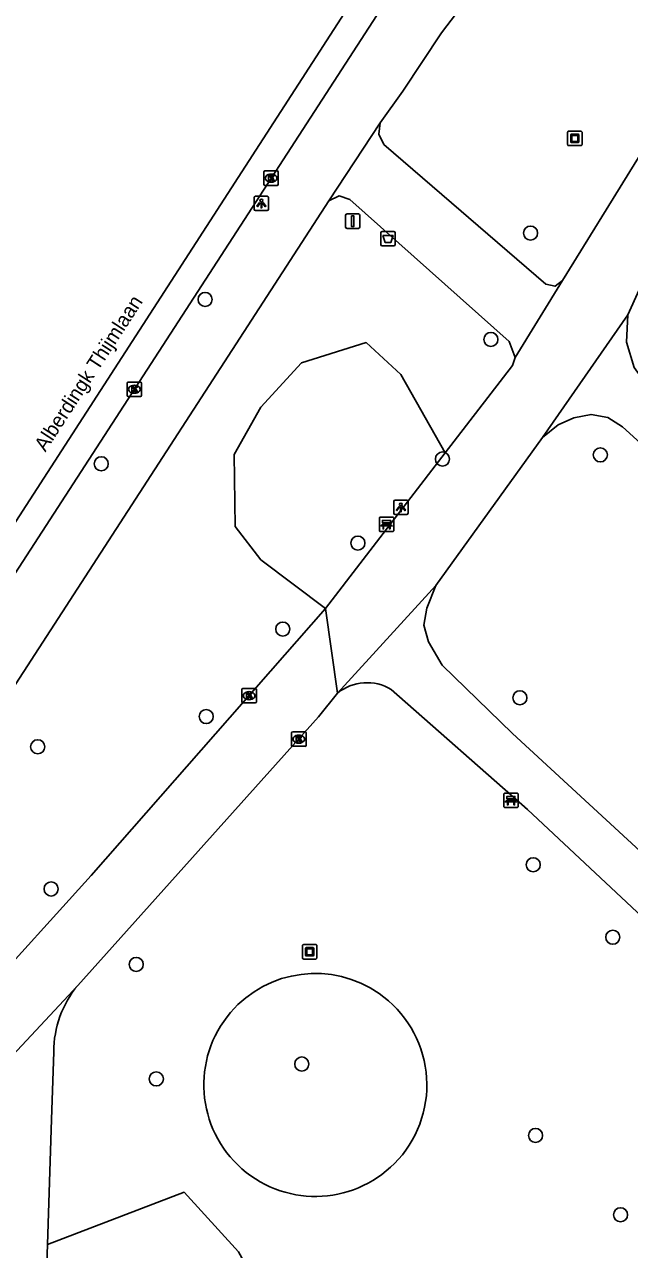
# Model space of a CAD drawing. Extents: x 161402 to 161933, y 381650 to 382313.
# Drawn here: x 161545.5 to 161587.5, y 381991 to 382075.9 of the extents above; entities that cross this region are included whole.
import ezdxf

# ---------------------------------------------------------------- set-up
doc = ezdxf.new("R2010")
doc.units = 0
for name, color, linetype in [('IMGEO_Afvalbak', 7, 'Continuous'), ('IMGEO_Bank', 7, 'Continuous'), ('IMGEO_Boom', 7, 'Continuous'), ('IMGEO_Groenvoorziening', 7, 'Continuous'), ('IMGEO_Kolk', 7, 'Continuous'), ('IMGEO_Kunstobject', 7, 'Continuous'), ('IMGEO_Lichtpunt', 7, 'Continuous'), ('IMGEO_Openbare_ruimte_label', 7, 'Continuous'), ('IMGEO_Rijbaan_lokaal_gesloten', 7, 'Continuous'), ('IMGEO_Verkeersbordpaal', 7, 'Continuous'), ('IMGEO_Voetpad_gesloten', 7, 'Continuous'), ('IMGEO_Voetpad_open', 7, 'Continuous')]:
    doc.layers.add(name, color=color, linetype=linetype)

msp = doc.modelspace()

# ---------------------------------------------------------------- linework, layer by layer
at = {"layer": 'IMGEO_Afvalbak'}
for p, q in [((161570.326, 382061.557), (161571.116, 382061.557)), ((161571.116, 382061.557), (161570.326, 382061.557)), ((161570.226, 382060.657), (161570.226, 382061.457)), ((161570.226, 382061.457), (161570.226, 382060.657)), ((161571.216, 382061.457), (161571.216, 382060.657)), ((161571.216, 382060.657), (161571.216, 382061.457)), ((161571.116, 382060.557), (161570.326, 382060.557)), ((161570.326, 382060.557), (161571.116, 382060.557))]:
    msp.add_line(p, q, dxfattribs=at)
msp.add_lwpolyline([(161570.369, 382061.271), (161571.073, 382061.271), (161570.924, 382060.801), (161570.518, 382060.801), (161570.369, 382061.271)], dxfattribs=at)
for centre, start, end in [((161570.326, 382061.457), 90, 180), ((161570.326, 382061.457), 90, 180), ((161571.116, 382061.457), 0, 90), ((161571.116, 382061.457), 360, 90), ((161570.326, 382060.657), 180, 270), ((161570.326, 382060.657), 180, 270), ((161571.116, 382060.657), 270, 0), ((161571.116, 382060.657), 270, 0)]:
    msp.add_arc(centre, 0.1, start, end, dxfattribs=at)
at = {"layer": 'IMGEO_Bank'}
for p, q in [((161570.122, 382040.825), (161570.122, 382041.666)), ((161570.122, 382041.666), (161570.122, 382040.825)), ((161570.197, 382041.75), (161571.038, 382041.75)), ((161571.038, 382041.75), (161570.197, 382041.75)), ((161570.431, 382041.256), (161570.431, 382041.362)), ((161570.475, 382041.362), (161570.475, 382041.256)), ((161570.763, 382041.368), (161570.481, 382041.368)), ((161570.481, 382041.25), (161570.763, 382041.25)), ((161570.769, 382041.256), (161570.769, 382041.362)), ((161570.813, 382041.362), (161570.813, 382041.256)), ((161571.122, 382041.675), (161571.122, 382040.834)), ((161571.122, 382040.834), (161571.122, 382041.675)), ((161571.047, 382040.75), (161570.206, 382040.75)), ((161570.206, 382040.75), (161571.047, 382040.75)), ((161570.819, 382041.148), (161570.426, 382041.148)), ((161578.746, 382021.695), (161578.746, 382022.536)), ((161578.746, 382022.536), (161578.746, 382021.695)), ((161578.821, 382022.62), (161579.662, 382022.62)), ((161579.662, 382022.62), (161578.821, 382022.62)), ((161579.746, 382022.545), (161579.746, 382021.704)), ((161579.746, 382021.704), (161579.746, 382022.545)), ((161579.443, 382022.018), (161579.05, 382022.018)), ((161579.055, 382022.126), (161579.055, 382022.232)), ((161579.099, 382022.232), (161579.099, 382022.126)), ((161579.387, 382022.238), (161579.105, 382022.238)), ((161579.105, 382022.12), (161579.387, 382022.12)), ((161579.393, 382022.126), (161579.393, 382022.232)), ((161579.437, 382022.232), (161579.437, 382022.126)), ((161579.671, 382021.62), (161578.83, 382021.62)), ((161578.83, 382021.62), (161579.671, 382021.62))]:
    msp.add_line(p, q, dxfattribs=at)
for points in [[(161570.369, 382041.148), (161570.227, 382041.148), (161570.339, 382041.25), (161570.425, 382041.25)], [(161570.425, 382041.368), (161570.339, 382041.368), (161570.339, 382041.529), (161570.902, 382041.529), (161570.902, 382041.368), (161570.819, 382041.368)], [(161570.819, 382041.25), (161570.902, 382041.25), (161571.014, 382041.148), (161570.875, 382041.148)], [(161570.419, 382041.141), (161570.419, 382040.934), (161570.376, 382040.934), (161570.376, 382041.141)], [(161570.869, 382041.141), (161570.869, 382040.934), (161570.825, 382040.934), (161570.825, 382041.141)], [(161578.993, 382022.018), (161578.851, 382022.018), (161578.963, 382022.12), (161579.049, 382022.12)], [(161579.049, 382022.238), (161578.963, 382022.238), (161578.963, 382022.399), (161579.526, 382022.399), (161579.526, 382022.238), (161579.443, 382022.238)], [(161579.043, 382022.011), (161579.043, 382021.804), (161579, 382021.804), (161579, 382022.011)], [(161579.443, 382022.12), (161579.526, 382022.12), (161579.638, 382022.018), (161579.499, 382022.018)], [(161579.493, 382022.011), (161579.493, 382021.804), (161579.449, 382021.804), (161579.449, 382022.011)]]:
    msp.add_lwpolyline(points, dxfattribs=at)
for centre, radius, start, end in [((161570.2, 382041.672), 0.0779, 92.4484, 184.28452), ((161570.2, 382041.672), 0.0779, 92.4484, 184.28452), ((161570.424, 382041.361), 0.00671, 2.89567, 87.10433), ((161570.424, 382041.257), 0.00671, 272.89567, 357.10433), ((161570.481, 382041.361), 0.00671, 92.89567, 177.10433), ((161570.481, 382041.257), 0.00671, 182.89567, 267.10433), ((161570.763, 382041.361), 0.00671, 2.89567, 87.10433), ((161570.763, 382041.257), 0.00671, 272.89567, 357.10433), ((161570.82, 382041.361), 0.00671, 92.89567, 177.10433), ((161570.82, 382041.257), 0.00671, 182.89567, 267.10433), ((161571.044, 382041.672), 0.0779, 2.4484, 94.28452), ((161571.044, 382041.672), 0.0779, 2.4484, 94.28452), ((161570.2, 382040.828), 0.0779, 182.4484, 274.28452), ((161570.2, 382040.828), 0.0779, 182.4484, 274.28452), ((161570.369, 382041.141), 0.00671, 2.89567, 87.10433), ((161570.426, 382041.141), 0.00671, 92.89567, 177.10433), ((161570.818, 382041.141), 0.00671, 2.89567, 87.10433), ((161570.875, 382041.141), 0.00671, 92.89567, 177.10433), ((161571.044, 382040.828), 0.0779, 272.4484, 4.28452), ((161571.044, 382040.828), 0.0779, 272.4484, 4.28452), ((161578.824, 382022.542), 0.0779, 92.4484, 184.28452), ((161578.824, 382022.542), 0.0779, 92.4484, 184.28452), ((161579.668, 382022.542), 0.0779, 2.4484, 94.28452), ((161579.668, 382022.542), 0.0779, 2.4484, 94.28452), ((161578.824, 382021.698), 0.0779, 182.4484, 274.28452), ((161578.824, 382021.698), 0.0779, 182.4484, 274.28452), ((161578.993, 382022.011), 0.00671, 2.89567, 87.10433), ((161579.05, 382022.011), 0.00671, 92.89567, 177.10433), ((161579.048, 382022.231), 0.00671, 2.89567, 87.10433), ((161579.048, 382022.127), 0.00671, 272.89567, 357.10433), ((161579.105, 382022.231), 0.00671, 92.89567, 177.10433), ((161579.105, 382022.127), 0.00671, 182.89567, 267.10433), ((161579.387, 382022.231), 0.00671, 2.89567, 87.10433), ((161579.387, 382022.127), 0.00671, 272.89567, 357.10433), ((161579.444, 382022.231), 0.00671, 92.89567, 177.10433), ((161579.444, 382022.127), 0.00671, 182.89567, 267.10433), ((161579.442, 382022.011), 0.00671, 2.89567, 87.10433), ((161579.499, 382022.011), 0.00671, 92.89567, 177.10433), ((161579.668, 382021.698), 0.0779, 272.4484, 4.28452), ((161579.668, 382021.698), 0.0779, 272.4484, 4.28452)]:
    msp.add_arc(centre, radius, start, end, dxfattribs=at)
at = {"layer": 'IMGEO_Boom'}
for centre in [(161580.604, 382061.45), (161558.047, 382056.845), (161577.855, 382054.076), (161574.5, 382045.785), (161585.441, 382046.074), (161550.846, 382045.454), (161568.634, 382039.959), (161563.429, 382033.996), (161579.862, 382029.231), (161558.123, 382027.931), (161546.441, 382025.837), (161580.786, 382017.659), (161547.37, 382015.978), (161586.303, 382012.631), (161553.269, 382010.749), (161564.748, 382003.843), (161554.661, 382002.809), (161580.95, 381998.893), (161586.845, 381993.392)]:
    msp.add_circle(centre, 0.489, dxfattribs=at)
at = {"layer": 'IMGEO_Groenvoorziening'}
for points in [[(161566.397, 382035.429), (161561.912, 382038.8), (161560.125, 382041.115), (161560.053, 382046.091), (161561.918, 382049.386), (161564.736, 382052.445), (161569.199, 382053.861), (161571.62, 382051.637), (161574.693, 382046.208)], [(161547.11, 381991.32), (161556.598, 381994.953), (161560.35, 381990.824), (161562.832, 381986.367), (161564.352, 381977.941)]]:
    msp.add_lwpolyline(points, dxfattribs=at)
for centre, radius, start, end in [((161565.687, 382002.391), 7.731, 55.08218, 139.41843), ((161565.685, 382002.391), 7.732, 318.21125, 55.07186), ((161565.689, 382002.394), 7.731, 139.44695, 318.1791)]:
    msp.add_arc(centre, radius, start, end, dxfattribs=at)
at = {"layer": 'IMGEO_Kolk'}
for p, q in [((161562.118, 382064.83), (161562.118, 382065.682)), ((161562.193, 382065.756), (161563.045, 382065.756)), ((161562.629, 382064.976), (161562.604, 382064.976)), ((161562.606, 382065.536), (161562.631, 382065.536)), ((161563.119, 382065.682), (161563.119, 382064.83)), ((161563.045, 382064.756), (161562.193, 382064.756)), ((161552.636, 382050.194), (161552.636, 382051.046)), ((161552.711, 382051.12), (161553.563, 382051.12)), ((161553.124, 382050.9), (161553.149, 382050.9)), ((161553.637, 382051.046), (161553.637, 382050.194)), ((161553.563, 382050.12), (161552.711, 382050.12)), ((161553.147, 382050.34), (161553.122, 382050.34)), ((161560.595, 382028.951), (161560.595, 382029.803)), ((161560.67, 382029.877), (161561.522, 382029.877)), ((161561.083, 382029.657), (161561.108, 382029.657)), ((161561.596, 382029.803), (161561.596, 382028.951)), ((161561.522, 382028.877), (161560.67, 382028.877)), ((161561.106, 382029.097), (161561.081, 382029.097)), ((161564.039, 382025.941), (161564.039, 382026.793)), ((161564.114, 382026.867), (161564.966, 382026.867)), ((161565.04, 382026.793), (161565.04, 382025.941)), ((161564.55, 382026.087), (161564.525, 382026.087)), ((161564.527, 382026.647), (161564.552, 382026.647)), ((161564.966, 382025.867), (161564.114, 382025.867))]:
    msp.add_line(p, q, dxfattribs=at)
for points in [[(161562.118, 382064.83), (161562.118, 382065.682)], [(161562.193, 382065.756), (161563.045, 382065.756)], [(161562.439, 382065.456), (161562.562, 382065.456), (161562.562, 382065.305), (161562.692, 382065.456), (161562.856, 382065.456), (161562.71, 382065.305), (161562.863, 382065.056), (161562.711, 382065.056), (161562.626, 382065.22), (161562.562, 382065.153), (161562.562, 382065.056), (161562.439, 382065.056), (161562.439, 382065.456)], [(161563.119, 382065.682), (161563.119, 382064.83)], [(161563.045, 382064.756), (161562.193, 382064.756)], [(161552.636, 382050.194), (161552.636, 382051.046)], [(161552.711, 382051.12), (161553.563, 382051.12)], [(161552.957, 382050.82), (161553.08, 382050.82), (161553.08, 382050.669), (161553.21, 382050.82), (161553.374, 382050.82), (161553.228, 382050.669), (161553.381, 382050.42), (161553.229, 382050.42), (161553.144, 382050.584), (161553.08, 382050.517), (161553.08, 382050.42), (161552.957, 382050.42), (161552.957, 382050.82)], [(161553.637, 382051.046), (161553.637, 382050.194)], [(161553.563, 382050.12), (161552.711, 382050.12)], [(161560.595, 382028.951), (161560.595, 382029.803)], [(161560.67, 382029.877), (161561.522, 382029.877)], [(161560.916, 382029.577), (161561.039, 382029.577), (161561.039, 382029.426), (161561.169, 382029.577), (161561.333, 382029.577), (161561.187, 382029.426), (161561.34, 382029.177), (161561.188, 382029.177), (161561.103, 382029.341), (161561.039, 382029.274), (161561.039, 382029.177), (161560.916, 382029.177), (161560.916, 382029.577)], [(161561.596, 382029.803), (161561.596, 382028.951)], [(161561.522, 382028.877), (161560.67, 382028.877)], [(161564.039, 382025.941), (161564.039, 382026.793)], [(161564.114, 382026.867), (161564.966, 382026.867)], [(161565.04, 382026.793), (161565.04, 382025.941)], [(161564.36, 382026.567), (161564.483, 382026.567), (161564.483, 382026.416), (161564.613, 382026.567), (161564.777, 382026.567), (161564.631, 382026.416), (161564.784, 382026.167), (161564.632, 382026.167), (161564.547, 382026.331), (161564.483, 382026.264), (161564.483, 382026.167), (161564.36, 382026.167), (161564.36, 382026.567)], [(161564.966, 382025.867), (161564.114, 382025.867)]]:
    msp.add_lwpolyline(points, dxfattribs=at)
for centre, start, end in [((161562.195, 382065.68), 91.55205, 178.44795), ((161562.195, 382065.68), 91.55205, 178.44795), ((161563.043, 382065.68), 1.55205, 88.44795), ((161563.043, 382065.68), 1.55205, 88.44795), ((161562.195, 382064.832), 181.55205, 268.44795), ((161562.195, 382064.832), 181.55205, 268.44795), ((161563.043, 382064.832), 271.55205, 358.44795), ((161563.043, 382064.832), 271.55205, 358.44795), ((161552.713, 382051.044), 91.55205, 178.44795), ((161552.713, 382051.044), 91.55205, 178.44795), ((161553.561, 382051.044), 1.55205, 88.44795), ((161553.561, 382051.044), 1.55205, 88.44795), ((161552.713, 382050.196), 181.55205, 268.44795), ((161552.713, 382050.196), 181.55205, 268.44795), ((161553.561, 382050.196), 271.55205, 358.44795), ((161553.561, 382050.196), 271.55205, 358.44795), ((161560.672, 382029.801), 91.55205, 178.44795), ((161560.672, 382029.801), 91.55205, 178.44795), ((161561.52, 382029.801), 1.55205, 88.44795), ((161561.52, 382029.801), 1.55205, 88.44795), ((161560.672, 382028.953), 181.55205, 268.44795), ((161560.672, 382028.953), 181.55205, 268.44795), ((161561.52, 382028.953), 271.55205, 358.44795), ((161561.52, 382028.953), 271.55205, 358.44795), ((161564.116, 382026.791), 91.55205, 178.44795), ((161564.116, 382026.791), 91.55205, 178.44795), ((161564.964, 382026.791), 1.55205, 88.44795), ((161564.964, 382026.791), 1.55205, 88.44795), ((161564.116, 382025.943), 181.55205, 268.44795), ((161564.116, 382025.943), 181.55205, 268.44795), ((161564.964, 382025.943), 271.55205, 358.44795), ((161564.964, 382025.943), 271.55205, 358.44795)]:
    msp.add_arc(centre, 0.0765, start, end, dxfattribs=at)
for centre, major_axis, ratio, start_param, end_param in [((161562.605, 382065.256), (-0.387, 0.002), 0.722429, 4.712389, 7.853982), ((161562.63, 382065.256), (-0.39, 0.002), 0.717154, 1.570796, 4.712389), ((161553.123, 382050.62), (-0.387, 0.002), 0.722429, 4.712389, 7.853982), ((161553.148, 382050.62), (-0.39, 0.002), 0.717154, 1.570796, 4.712389), ((161561.082, 382029.377), (-0.387, 0.002), 0.722429, 4.712389, 7.853982), ((161561.107, 382029.377), (-0.39, 0.002), 0.717154, 1.570796, 4.712389), ((161564.526, 382026.367), (-0.387, 0.002), 0.722429, 4.712389, 7.853982), ((161564.551, 382026.367), (-0.39, 0.002), 0.717154, 1.570796, 4.712389)]:
    msp.add_ellipse(centre, major_axis=major_axis, ratio=ratio, start_param=start_param, end_param=end_param, dxfattribs=at)
at = {"layer": 'IMGEO_Kunstobject'}
for p, q in [((161583.173, 382068.427), (161583.173, 382067.586)), ((161583.173, 382068.427), (161583.173, 382067.586)), ((161584.089, 382068.511), (161583.248, 382068.511)), ((161584.089, 382068.511), (161583.248, 382068.511)), ((161584.173, 382067.595), (161584.173, 382068.436)), ((161584.173, 382067.595), (161584.173, 382068.436)), ((161583.257, 382067.511), (161584.098, 382067.511)), ((161583.257, 382067.511), (161584.098, 382067.511)), ((161583.387, 382067.775), (161583.387, 382068.249)), ((161583.437, 382068.299), (161583.911, 382068.299)), ((161583.911, 382067.725), (161583.437, 382067.725)), ((161583.467, 382068.199), (161583.467, 382067.825)), ((161583.861, 382068.219), (161583.487, 382068.219)), ((161583.487, 382067.805), (161583.861, 382067.805)), ((161583.881, 382067.825), (161583.881, 382068.199)), ((161583.961, 382068.249), (161583.961, 382067.775)), ((161564.792, 382012.039), (161564.792, 382011.198)), ((161564.792, 382012.039), (161564.792, 382011.198)), ((161565.708, 382012.123), (161564.867, 382012.123)), ((161565.708, 382012.123), (161564.867, 382012.123)), ((161565.006, 382011.387), (161565.006, 382011.861)), ((161565.056, 382011.911), (161565.53, 382011.911)), ((161565.086, 382011.811), (161565.086, 382011.437)), ((161565.48, 382011.831), (161565.106, 382011.831)), ((161565.5, 382011.437), (161565.5, 382011.811)), ((161565.58, 382011.861), (161565.58, 382011.387)), ((161565.792, 382011.207), (161565.792, 382012.048)), ((161565.792, 382011.207), (161565.792, 382012.048)), ((161564.876, 382011.123), (161565.717, 382011.123)), ((161564.876, 382011.123), (161565.717, 382011.123)), ((161565.53, 382011.337), (161565.056, 382011.337)), ((161565.106, 382011.417), (161565.48, 382011.417))]:
    msp.add_line(p, q, dxfattribs=at)
for centre, radius, start, end in [((161583.251, 382068.433), 0.0779, 92.4484, 184.28452), ((161583.251, 382068.433), 0.0779, 92.4484, 184.28452), ((161584.095, 382068.433), 0.0779, 2.4484, 94.28452), ((161584.095, 382068.433), 0.0779, 2.4484, 94.28452), ((161583.251, 382067.589), 0.0779, 182.4484, 274.28452), ((161583.251, 382067.589), 0.0779, 182.4484, 274.28452), ((161583.437, 382068.249), 0.05, 90, 180), ((161583.437, 382067.775), 0.05, 180, 270), ((161583.487, 382068.199), 0.02, 90, 180), ((161583.487, 382067.825), 0.02, 180, 270), ((161583.861, 382068.199), 0.02, 360, 90), ((161583.861, 382067.825), 0.02, 270, 0), ((161583.911, 382068.249), 0.05, 360, 90), ((161583.911, 382067.775), 0.05, 270, 0), ((161584.095, 382067.589), 0.0779, 272.4484, 4.28452), ((161584.095, 382067.589), 0.0779, 272.4484, 4.28452), ((161564.87, 382012.045), 0.0779, 92.4484, 184.28452), ((161564.87, 382012.045), 0.0779, 92.4484, 184.28452), ((161565.056, 382011.861), 0.05, 90, 180), ((161565.106, 382011.811), 0.02, 90, 180), ((161565.106, 382011.437), 0.02, 180, 270), ((161565.48, 382011.811), 0.02, 360, 90), ((161565.48, 382011.437), 0.02, 270, 0), ((161565.53, 382011.861), 0.05, 360, 90), ((161565.714, 382012.045), 0.0779, 2.4484, 94.28452), ((161565.714, 382012.045), 0.0779, 2.4484, 94.28452), ((161564.87, 382011.201), 0.0779, 182.4484, 274.28452), ((161564.87, 382011.201), 0.0779, 182.4484, 274.28452), ((161565.056, 382011.387), 0.05, 180, 270), ((161565.53, 382011.387), 0.05, 270, 0), ((161565.714, 382011.201), 0.0779, 272.4484, 4.28452), ((161565.714, 382011.201), 0.0779, 272.4484, 4.28452)]:
    msp.add_arc(centre, radius, start, end, dxfattribs=at)
at = {"layer": 'IMGEO_Lichtpunt'}
for p, q in [((161561.445, 382063.904), (161561.445, 382063.097)), ((161561.445, 382063.904), (161561.445, 382063.097)), ((161562.347, 382063.999), (161561.539, 382063.999)), ((161562.347, 382063.999), (161561.539, 382063.999)), ((161562.441, 382063.097), (161562.441, 382063.904)), ((161562.441, 382063.097), (161562.441, 382063.904)), ((161561.539, 382063.003), (161562.347, 382063.003)), ((161561.539, 382063.003), (161562.347, 382063.003)), ((161572.018, 382042.932), (161571.21, 382042.932)), ((161572.018, 382042.932), (161571.21, 382042.932)), ((161571.116, 382042.837), (161571.116, 382042.03)), ((161571.116, 382042.837), (161571.116, 382042.03)), ((161572.112, 382042.03), (161572.112, 382042.837)), ((161572.112, 382042.03), (161572.112, 382042.837)), ((161571.21, 382041.936), (161572.018, 382041.936)), ((161571.21, 382041.936), (161572.018, 382041.936))]:
    msp.add_line(p, q, dxfattribs=at)
for points in [[(161561.819, 382063.568), (161561.858, 382063.54), (161561.67, 382063.278), (161561.632, 382063.305), (161561.819, 382063.568)], [(161561.921, 382063.52), (161561.968, 382063.52), (161561.968, 382063.198), (161561.921, 382063.198), (161561.921, 382063.52)], [(161562.031, 382063.54), (161562.069, 382063.567), (161562.256, 382063.305), (161562.217, 382063.277), (161562.031, 382063.54)], [(161571.49, 382042.501), (161571.529, 382042.473), (161571.341, 382042.211), (161571.303, 382042.238), (161571.49, 382042.501)], [(161571.592, 382042.453), (161571.639, 382042.453), (161571.639, 382042.131), (161571.592, 382042.131), (161571.592, 382042.453)], [(161571.702, 382042.473), (161571.74, 382042.5), (161571.927, 382042.238), (161571.888, 382042.21), (161571.702, 382042.473)]]:
    msp.add_lwpolyline(points, dxfattribs=at)
for centre in [(161561.944, 382063.702), (161571.615, 382042.635)]:
    msp.add_circle(centre, 0.0994, dxfattribs=at)
for centre, start, end in [((161561.539, 382063.904), 90, 180), ((161561.539, 382063.904), 90, 180), ((161562.347, 382063.904), 0, 90), ((161562.347, 382063.904), 0, 90), ((161561.539, 382063.097), 180, 270), ((161561.539, 382063.097), 180, 270), ((161562.347, 382063.097), 270, 0), ((161562.347, 382063.097), 270, 360), ((161571.21, 382042.837), 90, 180), ((161571.21, 382042.837), 90, 180), ((161572.018, 382042.837), 0, 90), ((161572.018, 382042.837), 0, 90), ((161571.21, 382042.03), 180, 270), ((161571.21, 382042.03), 180, 270), ((161572.018, 382042.03), 270, 0), ((161572.018, 382042.03), 270, 360)]:
    msp.add_arc(centre, 0.0946, start, end, dxfattribs=at)
at = {"layer": 'IMGEO_Rijbaan_lokaal_gesloten'}
for points in [[(161578.467, 382089.284), (161576.388, 382086.507), (161541.352, 382032.43)], [(161539.75, 382033.486), (161574.317, 382086.95)]]:
    msp.add_lwpolyline(points, dxfattribs=at)
at = {"layer": 'IMGEO_Verkeersbordpaal'}
for p, q in [((161567.781, 382061.874), (161567.781, 382062.674)), ((161567.781, 382062.674), (161567.781, 382061.874)), ((161567.881, 382062.774), (161568.671, 382062.774)), ((161568.671, 382062.774), (161567.881, 382062.774)), ((161568.771, 382062.674), (161568.771, 382061.874)), ((161568.771, 382061.874), (161568.771, 382062.674)), ((161568.671, 382061.774), (161567.881, 382061.774)), ((161567.881, 382061.774), (161568.671, 382061.774))]:
    msp.add_line(p, q, dxfattribs=at)
msp.add_lwpolyline([(161568.201, 382062.649), (161568.351, 382062.649), (161568.351, 382061.899), (161568.201, 382061.899), (161568.201, 382062.649)], dxfattribs=at)
for centre, start, end in [((161567.881, 382062.674), 90, 180), ((161567.881, 382062.674), 90, 180), ((161568.671, 382062.674), 0, 90), ((161568.671, 382062.674), 360, 90), ((161567.881, 382061.874), 180, 270), ((161567.881, 382061.874), 180, 270), ((161568.671, 382061.874), 270, 0), ((161568.671, 382061.874), 270, 0)]:
    msp.add_arc(centre, 0.1, start, end, dxfattribs=at)
at = {"layer": 'IMGEO_Voetpad_gesloten'}
for points in [[(161620.728, 382112.027), (161616.48, 382107.434), (161612.452, 382102.646), (161608.254, 382097.285), (161598.47, 382083.033), (161592.764, 382074.245), (161582.818, 382058.156)], [(161570.174, 382069.09), (161566.628, 382063.688)], [(161582.818, 382058.156), (161582.301, 382057.757), (161581.666, 382057.913), (161570.428, 382067.596), (161570.085, 382068.306), (161570.174, 382069.09)], [(161587.35, 382055.783), (161588.122, 382057.524), (161592.51, 382064.912)], [(161566.628, 382063.688), (161567.337, 382064.038), (161568.086, 382063.783), (161579.122, 382053.921), (161579.545, 382052.829)], [(161582.818, 382058.156), (161579.545, 382052.829)], [(161587.35, 382055.783), (161581.425, 382047.268)], [(161618.822, 382023.52), (161588.839, 382050.654), (161587.788, 382052.14), (161587.259, 382053.881), (161587.35, 382055.783)], [(161579.545, 382052.829), (161579.356, 382052.267), (161574.693, 382046.208)], [(161581.425, 382047.268), (161582.51, 382048.162), (161583.611, 382048.649), (161584.795, 382048.872), (161585.966, 382048.656), (161586.971, 382048.017), (161620.495, 382017.54)], [(161574.039, 382037.028), (161581.425, 382047.268)], [(161574.693, 382046.208), (161566.397, 382035.429)], [(161567.213, 382029.55), (161574.039, 382037.028)], [(161606.792, 382001.445), (161579.342, 382026.767), (161574.473, 382031.494), (161573.524, 382033.118), (161573.21, 382034.265), (161573.408, 382035.438), (161574.039, 382037.028)], [(161566.397, 382035.429), (161550.139, 382016.903), (161534.836, 382000), (161522.917, 381986.45), (161514.478, 381976.419), (161513.027, 381974.379)], [(161566.397, 382035.429), (161567.213, 382029.55)], [(161549.221, 382009.294), (161565.913, 382027.909), (161567.213, 382029.55)], [(161570.953, 382029.807), (161580.388, 382021.484), (161590.516, 382012.008), (161603.06, 382000.577)], [(161549.221, 382009.294), (161544.361, 382004.097)], [(161547.11, 381991.32), (161547.398, 382000), (161547.553, 382004.687)], [(161547.032, 381988.57), (161547.11, 381991.32)]]:
    msp.add_lwpolyline(points, dxfattribs=at)
for centre, radius, start, end in [((161569.265, 382027.029), 3.25, 58.7134, 129.14858), ((161554.751, 382004.686), 7.198, 140.19796, 179.99568)]:
    msp.add_arc(centre, radius, start, end, dxfattribs=at)
at = {"layer": 'IMGEO_Voetpad_open'}
for points in [[(161570.174, 382069.09), (161571.745, 382071.279), (161574.421, 382075.333), (161608.435, 382119.953)], [(161566.628, 382063.688), (161525.324, 382000), (161509.956, 381976.304)]]:
    msp.add_lwpolyline(points, dxfattribs=at)

# ---------------------------------------------------------------- texts
at = {"layer": 'IMGEO_Openbare_ruimte_label'}
msp.add_text('Alberdingk Thijmlaan', height=1, rotation=57.04099, dxfattribs=at).set_placement((161546.972, 382046.232))

doc.saveas('drawing.dxf')
